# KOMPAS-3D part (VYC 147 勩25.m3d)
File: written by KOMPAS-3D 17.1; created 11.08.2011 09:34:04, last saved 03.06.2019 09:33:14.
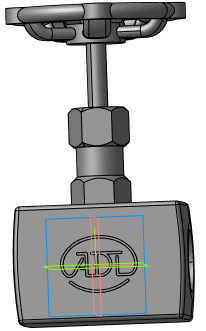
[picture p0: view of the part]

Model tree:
1. Плоскость XY
2. Плоскость ZX
3. Плоскость ZY
4. Ось X
5. Ось Y
6. Ось Z
7. Начало координат
8. Операция без истории:2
